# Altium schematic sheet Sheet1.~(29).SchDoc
size A
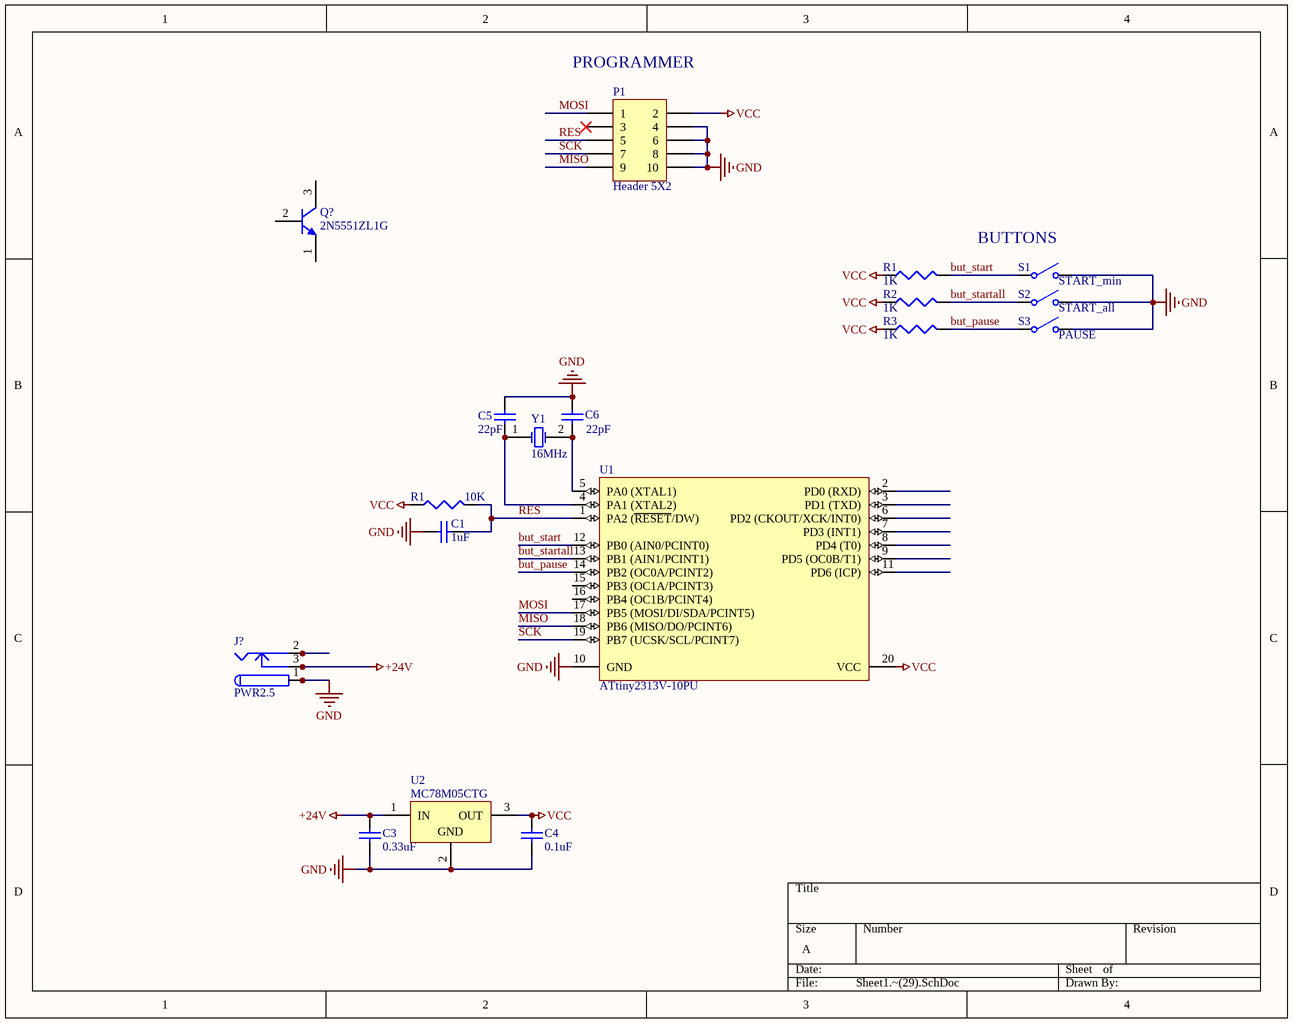
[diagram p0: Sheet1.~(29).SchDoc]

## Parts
(Parts that share a designator on the sheet are numbered #1, #2 ... from top to bottom, then left to right.)
C1  value 1uF  [1608[0603]]  (hidden comment: Cap Semi)
C3  value 0.33uF  [1608[0603]]  (hidden comment: Cap Semi)
C4  value 0.1uF  [1608[0603]]  (hidden comment: Cap Semi)
C5  value 22pF  [1608[0603]]  (hidden comment: Cap Semi)
C6  value 22pF  [1608[0603]]  (hidden comment: Cap Semi)
J?  PWR2.5  [KLD-0202]
P1  Header 5X2  [HDR2X5]
Q?  2N5551ZL1G  [ONSC-TO-92-3-29-11_AM_BL]
R1#1  value 1K  [J1-0603]  (hidden comment: Res3)
R1#2  value 10K  [J1-0603]  (hidden comment: Res3)
R2  value 1K  [J1-0603]  (hidden comment: Res3)
R3  value 1K  [J1-0603]  (hidden comment: Res3)
S1  START_min  [SPST-2]
S2  START_all  [SPST-2]
S3  PAUSE  [SPST-2]
U1  ATtiny2313V-10PU  [20P3]
U2  MC78M05CTG  [TO220]
Y1  16MHz  [HC-49U]

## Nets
+24V: C3.2 J?.3 J?.3A J?.3B U2.1(IN)
GND: C1.2 C3.1 C4.1 C5.1 C6.1 J?.1 J?.1A J?.1B P1.4 P1.6 P1.8 P1.10 S1.2(NO) S2.2(NO) S3.2(NO) U1.10(GND) U2.2(GND)
VCC: C4.2 P1.2 R1#1.1 R1#2.1 R2.1 R3.1 U1.20(VCC) U2.3(OUT)
but_pause: R3.2 S3.1(COMMON) U1.14(PB2_(OC0A/PCINT2))
but_start: R1#1.2 S1.1(COMMON) U1.12(PB0_(AIN0/PCINT0))
but_startall: R2.2 S2.1(COMMON) U1.13(PB1_(AIN1/PCINT1))
MISO: P1.9 U1.18(PB6_(MISO/DO/PCINT6))
MOSI: P1.1 U1.17(PB5_(MOSI/DI/SDA/PCINT5))
RES: C1.1 P1.5 R1#2.2 U1.1(PA2_(~{RESET}/DW))
SCK: P1.7 U1.19(PB7_(UCSK/SCL/PCINT7))
NetC5_2: C5.2 U1.4(PA1_(XTAL2)) Y1.1(OSC1)
NetC6_2: C6.2 U1.5(PA0_(XTAL1)) Y1.2(OSC2)
NetJ?_2: J?.2 J?.2A J?.2B

Not connected (* = marked no-connect by the designer): P1 3*; Q? 1(E) 2(B) 3(C); U1 2(PD0_(RXD)) 3(PD1_(TXD)) 6(PD2_(CKOUT/XCK/INT0)) 7(PD3_(INT1)) 8(PD4_(T0)) 9(PD5_(OC0B/T1)) 11(PD6_(ICP)) 15(PB3_(OC1A/PCINT3)) 16(PB4_(OC1B/PCINT4))

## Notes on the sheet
- (near P1) PROGRAMMER
- (near S1) BUTTONS

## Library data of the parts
C1 C3-C6 = Cap Semi: Capacitor (Semiconductor SIM Model)
J? = PWR2.5: Low Voltage Power Supply Connector
P1 = Header 5X2: Header, 5-Pin, Dual row
Q? = CMP-1048-01489-1: Amplifier Transistor, NPN Silicon, 3-Pin TO-92, Pb-Free, Ammo Box; Manufacturer: On Semiconductor; fT Min (MHz): 100; IC Continuous (A): 0.6
R1#1 R1#2 R2 R3 = Res3: Resistor
S1-S3 = SW-SPST: Single-Pole, Single-Throw Switch
U1 = CMP-0093-00017-1: Low Power tinyAVR® 8-Bit Microcontroller, 2K Flash Memory, 10MHz, Industrial Temperature, 20-Lead PDIP, Pb-Free
U2 = CMP-0244-00483-1: Positive Voltage Regulator, 5V, 3-Pin TO-220
Y1 = XTAL: Crystal Oscillator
